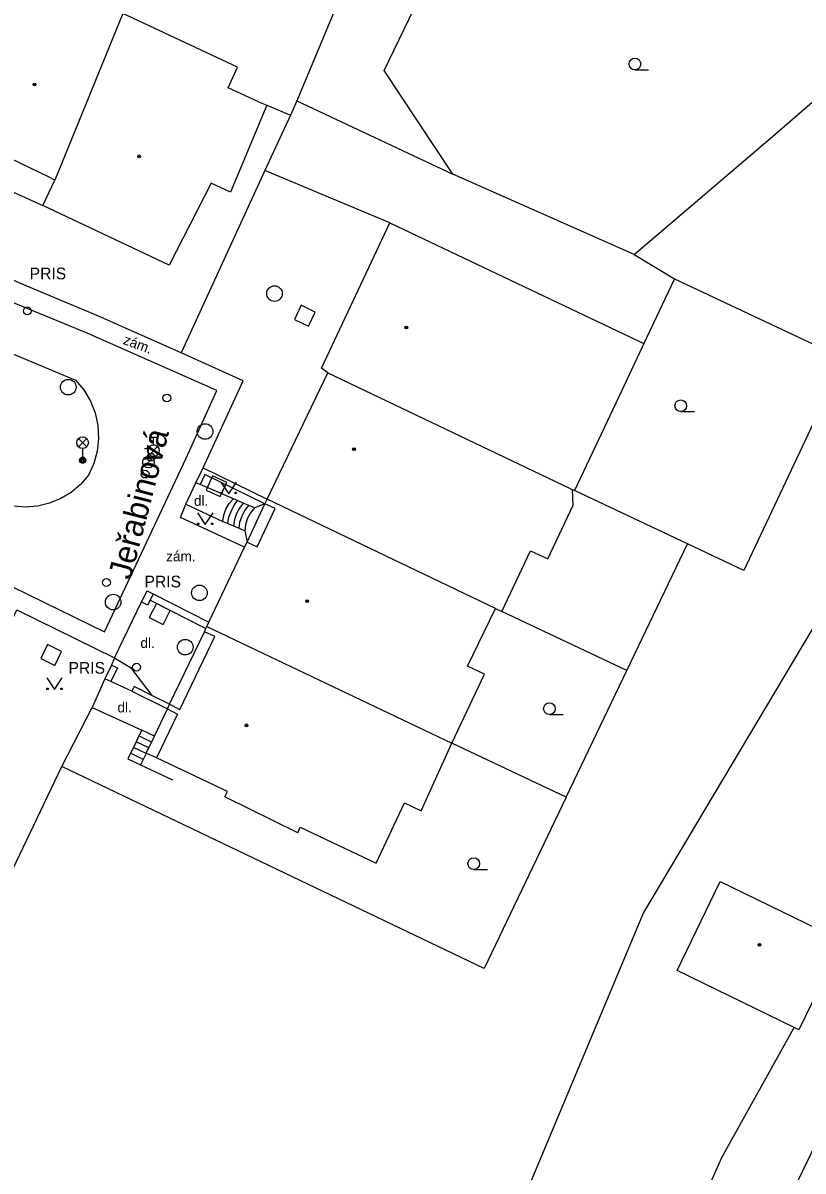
# Model space of a CAD drawing. Extents: x -600309 to -598967, y -1161267 to -1160292.
# Drawn here: x -599887.4 to -599837.4, y -1160784.7 to -1160711.1 of the extents above; entities that cross this region are included whole.
import ezdxf

# ---------------------------------------------------------------- set-up
doc = ezdxf.new("R2010")
doc.units = 0
for name, color, linetype in [('Level 10', 7, 'Continuous'), ('Level 11', 7, 'Continuous'), ('Level 24', 7, 'Continuous'), ('Level 26', 7, 'Continuous'), ('Level 27', 7, 'Continuous'), ('Level 28', 7, 'Continuous'), ('Level 33', 7, 'Continuous'), ('Level 36', 7, 'Continuous'), ('Level 39', 7, 'Continuous'), ('Level 40', 7, 'Continuous'), ('Level 42', 7, 'Continuous'), ('Level 5', 7, 'Continuous'), ('Level 50', 7, 'Continuous'), ('Level 51', 7, 'Continuous'), ('Level 52', 7, 'Continuous')]:
    doc.layers.add(name, color=color, linetype=linetype)

msp = doc.modelspace()

# ---------------------------------------------------------------- linework, layer by layer
at = {"layer": 'Level 10'}
for points in [[(-599941.84, -1160720.95), (-599921.83, -1160730.68), (-599912.84, -1160735.04), (-599897.82, -1160742.4699), (-599882.1599, -1160750.1), (-599876.92, -1160738.9699), (-599874.96, -1160734.65), (-599883.28, -1160730.96), (-599891.87, -1160727.45), (-599900.5, -1160724)], [(-599902.28, -1160726.6), (-599894.83, -1160729.46), (-599884.02, -1160733.98)], [(-599884.02, -1160733.98), (-599883.49, -1160734.61), (-599883.07, -1160735.32), (-599882.77, -1160736.08), (-599882.59, -1160736.89), (-599882.55, -1160737.71), (-599882.63, -1160738.53), (-599882.85, -1160739.32), (-599883.19, -1160740.07), (-599883.7, -1160740.6599), (-599884.3, -1160741.17), (-599884.9699, -1160741.57), (-599885.69, -1160741.87), (-599886.45, -1160742.05), (-599887.23, -1160742.11), (-599888.01, -1160742.05), (-599888.77, -1160741.87)]]:
    msp.add_lwpolyline(points, dxfattribs=at)
at = {"layer": 'Level 11'}
for points in [[(-599871.77, -1160716.37), (-599870.25, -1160717)], [(-599863.88, -1160723.9), (-599871.89, -1160720.55)], [(-599890.92, -1160726.29), (-599888.65, -1160721.63), (-599886.12, -1160722.79)], [(-599877.26, -1160732.23), (-599882.54, -1160729.87), (-599887.59, -1160727.77), (-599888.2199, -1160727.48)], [(-599875.85, -1160739.6), (-599873.27, -1160734.02), (-599877.26, -1160732.23)], [(-599876.32, -1160740.55), (-599875.85, -1160739.6)], [(-599871.88, -1160741.9), (-599875.73, -1160740.03), (-599876.04, -1160740.67)], [(-599875.85, -1160739.6), (-599871.74, -1160741.6)], [(-599876.95, -1160741.93), (-599876.32, -1160740.55)], [(-599876.04, -1160740.67), (-599876.32, -1160740.55)], [(-599873.9, -1160741.59), (-599876.04, -1160740.67)], [(-599874.57, -1160743.03), (-599874.52, -1160742.63), (-599874.38, -1160742.24), (-599874.17, -1160741.89), (-599873.9, -1160741.59)], [(-599874.27, -1160743.1599), (-599874.19, -1160742.77), (-599874.05, -1160742.39), (-599873.87, -1160742.03), (-599873.65, -1160741.7)], [(-599873.65, -1160741.7), (-599873.9, -1160741.59)], [(-599873.28, -1160741.86), (-599873.65, -1160741.7)], [(-599873.19, -1160744.69), (-599877.3, -1160742.79), (-599876.95, -1160741.93)], [(-599876.95, -1160741.93), (-599874.57, -1160743.03)], [(-599873.28, -1160741.86), (-599873.52, -1160742.18), (-599873.7, -1160742.53), (-599873.83, -1160742.9099), (-599873.9, -1160743.32)], [(-599873.54, -1160743.4699), (-599873.48, -1160743.07), (-599873.35, -1160742.68), (-599873.1599, -1160742.33), (-599872.9099, -1160742.01)], [(-599872.9099, -1160742.01), (-599873.28, -1160741.86)], [(-599872.54, -1160742.17), (-599872.81, -1160742.48), (-599873, -1160742.83), (-599873.12, -1160743.2199), (-599873.1599, -1160743.63)], [(-599872.54, -1160742.17), (-599872.9099, -1160742.01)], [(-599871.88, -1160741.9), (-599872.54, -1160742.17)], [(-599874.57, -1160743.03), (-599874.27, -1160743.1599)], [(-599874.27, -1160743.1599), (-599873.9, -1160743.32)], [(-599873.9, -1160743.32), (-599873.54, -1160743.4699)], [(-599873.54, -1160743.4699), (-599873.1599, -1160743.63)], [(-599873.1599, -1160743.63), (-599873.03, -1160744.36)], [(-599881.52, -1160751.78), (-599879.8, -1160748.19), (-599879.44, -1160747.4699), (-599879.04, -1160747.67), (-599875.4699, -1160749.49)], [(-599879.24, -1160748.08), (-599875.6599, -1160749.9)], [(-599890.39, -1160754.18), (-599887.79, -1160748.69), (-599881.52, -1160751.78)], [(-599881.52, -1160751.78), (-599881.7199, -1160752.25), (-599882.14, -1160753.11)], [(-599881.52, -1160751.78), (-599880.5, -1160752.4), (-599879.14, -1160754.18)], [(-599882.14, -1160753.11), (-599882.96, -1160754.95)], [(-599880.42, -1160753.9099), (-599881.76, -1160753.29), (-599882.14, -1160753.11)], [(-599879.14, -1160754.18), (-599880.27, -1160753.61), (-599880.42, -1160753.9099)], [(-599880.42, -1160753.9099), (-599878.13, -1160755.05)], [(-599877.99, -1160754.75), (-599879.14, -1160754.18)], [(-599882.96, -1160754.95), (-599879.78, -1160756.4099)], [(-599879.78, -1160756.4099), (-599879.96, -1160756.78)], [(-599878.9699, -1160756.8), (-599879.78, -1160756.4099)], [(-599880.13, -1160757.15), (-599880.31, -1160757.52)], [(-599879.96, -1160756.78), (-599880.13, -1160757.15)], [(-599879.33, -1160757.54), (-599880.13, -1160757.15)], [(-599879.15, -1160757.17), (-599879.96, -1160756.78)], [(-599880.49, -1160757.89), (-599880.6599, -1160758.25), (-599879.85, -1160758.63)], [(-599880.31, -1160757.52), (-599880.49, -1160757.89)], [(-599879.68, -1160758.28), (-599880.49, -1160757.89)], [(-599879.5, -1160757.9099), (-599880.31, -1160757.52)], [(-599879.5, -1160757.9099), (-599879.68, -1160758.28)], [(-599879.49, -1160757.88), (-599879.5, -1160757.9099)], [(-599879.68, -1160758.28), (-599879.85, -1160758.63)], [(-599879.85, -1160758.63), (-599877.8, -1160759.59)]]:
    msp.add_lwpolyline(points, dxfattribs=at)
at = {"layer": 'Level 24'}
for points in [[(-599879.4, -1160748.39), (-599879.8, -1160748.19)], [(-599879.04, -1160747.67), (-599879.24, -1160748.08), (-599879.4, -1160748.39)], [(-599881.34, -1160752.42), (-599881.76, -1160753.29)], [(-599881.7199, -1160752.25), (-599881.34, -1160752.42)]]:
    msp.add_lwpolyline(points, dxfattribs=at)
at = {"layer": 'Level 26'}
for points in [[(-599869.0934, -1160730.5163), (-599868.6637, -1160729.6134), (-599869.5666, -1160729.1837), (-599869.9963, -1160730.0866)], [(-599874.3263, -1160740.536), (-599875.234, -1160740.1163), (-599875.6537, -1160741.024), (-599874.746, -1160741.4437)], [(-599877.9477, -1160748.7409), (-599878.8391, -1160748.2877), (-599879.2923, -1160749.1791), (-599878.4009, -1160749.6323)], [(-599886.2495, -1160751.8174), (-599885.3526, -1160752.2595), (-599884.9105, -1160751.3626), (-599885.8074, -1160750.9205)]]:
    msp.add_lwpolyline(points, close=True, dxfattribs=at)
at = {"layer": 'Level 27'}
for centre in [(-599871.27, -1160728.43), (-599884.49, -1160734.43), (-599875.7199, -1160737.27), (-599876.08, -1160747.61), (-599881.61, -1160748.2), (-599876.99, -1160751.09)]:
    msp.add_circle(centre, 0.5, dxfattribs=at)
at = {"layer": 'Level 28'}
for p, q in [((-599879.28, -1160737.625), (-599878.78, -1160737.625)), ((-599879.03, -1160738.125), (-599879.03, -1160737.625)), ((-599879.6, -1160738.355), (-599879.1, -1160738.355)), ((-599879.35, -1160738.855), (-599879.35, -1160738.355)), ((-599879.288, -1160738.772), (-599878.758, -1160738.242)), ((-599879.608, -1160739.502), (-599879.078, -1160738.972))]:
    msp.add_line(p, q, dxfattribs=at)
for centre, radius in [((-599887.11, -1160729.54), 0.25), ((-599878.17, -1160735.12), 0.25), ((-599879.18, -1160738.92), 0.25), ((-599879.03, -1160738.5), 0.375), ((-599879.35, -1160739.23), 0.375), ((-599879.56, -1160740), 0.25), ((-599882.04, -1160746.95), 0.25), ((-599880.11, -1160752.37), 0.25)]:
    msp.add_circle(centre, radius, dxfattribs=at)
at = {"layer": 'Level 33'}
for p, q in [((-599883.835, -1160738.25), (-599883.305, -1160737.72)), ((-599883.835, -1160737.72), (-599883.305, -1160738.25)), ((-599883.57, -1160738.36), (-599883.57, -1160739.11))]:
    msp.add_line(p, q, dxfattribs=at)
for centre, radius in [((-599883.57, -1160737.985), 0.375), ((-599883.57, -1160739.11), 0.2), ((-599883.57, -1160739.11), 0.1445), ((-599883.57, -1160739.11), 0.0876)]:
    msp.add_circle(centre, radius, dxfattribs=at)
at = {"layer": 'Level 36'}
for p, q in [((-599848.17, -1160714.0949), (-599847.295, -1160714.0949)), ((-599845.23, -1160735.995), (-599844.355, -1160735.995)), ((-599853.65, -1160755.405), (-599852.775, -1160755.405)), ((-599858.5, -1160765.335), (-599857.625, -1160765.335))]:
    msp.add_line(p, q, dxfattribs=at)
for points in [[(-599874.7, -1160740.51), (-599874.2, -1160741.26), (-599873.7, -1160740.51)], [(-599876.21, -1160742.49), (-599875.71, -1160743.24), (-599875.21, -1160742.49)], [(-599885.87, -1160753.06), (-599885.37, -1160753.81), (-599884.87, -1160753.06)]]:
    msp.add_lwpolyline(points, dxfattribs=at)
for centre, radius in [((-599848.1701, -1160713.7198), 0.375), ((-599845.2301, -1160735.6199), 0.375), ((-599874.6502, -1160741.2098), 0.05), ((-599873.7508, -1160741.2098), 0.05), ((-599876.1602, -1160743.1898), 0.05), ((-599875.2608, -1160743.1898), 0.05), ((-599885.8202, -1160753.7598), 0.05), ((-599884.9208, -1160753.7598), 0.05), ((-599853.6501, -1160755.0299), 0.375), ((-599858.5001, -1160764.9599), 0.375)]:
    msp.add_circle(centre, radius, dxfattribs=at)
at = {"layer": 'Level 39'}
for centre, radius in [((-599886.65, -1160715.04), 0.09), ((-599886.65, -1160715.04), 0.0398), ((-599879.94, -1160719.64), 0.09), ((-599879.94, -1160719.64), 0.0398), ((-599862.82, -1160730.61), 0.09), ((-599862.82, -1160730.61), 0.0398), ((-599866.17, -1160738.4), 0.09), ((-599866.17, -1160738.4), 0.0398), ((-599869.17, -1160748.14), 0.09), ((-599869.17, -1160748.14), 0.0398), ((-599873.06, -1160756.1), 0.09), ((-599873.06, -1160756.1), 0.0398), ((-599840.18, -1160770.1599), 0.09), ((-599840.18, -1160770.1599), 0.0398)]:
    msp.add_circle(centre, radius, dxfattribs=at)
at = {"layer": 'Level 5'}
for points in [[(-599880.98, -1160710.48), (-599885.35, -1160721.1599)], [(-599873.63, -1160713.93), (-599880.98, -1160710.48)], [(-599874.24, -1160715.24), (-599873.63, -1160713.93)], [(-599872.3, -1160716.15), (-599874.24, -1160715.24)], [(-599871.77, -1160716.37), (-599874.09, -1160721.93)], [(-599872.3, -1160716.15), (-599871.77, -1160716.37)], [(-599885.76, -1160720.96), (-599888.73, -1160719.53)], [(-599886.12, -1160722.79), (-599885.35, -1160721.1599)], [(-599885.35, -1160721.1599), (-599885.76, -1160720.96)], [(-599875.32, -1160721.36), (-599878.01, -1160726.61)], [(-599874.09, -1160721.93), (-599875.32, -1160721.36)], [(-599878.01, -1160726.61), (-599886.12, -1160722.79)], [(-599868.26, -1160733.2199), (-599863.88, -1160723.9)], [(-599863.88, -1160723.9), (-599847.6, -1160731.63)], [(-599847.73, -1160731.9), (-599849.21, -1160735.05)], [(-599847.6, -1160731.63), (-599847.73, -1160731.9)], [(-599871.74, -1160741.6), (-599867.85, -1160733.51)], [(-599867.85, -1160733.51), (-599868.26, -1160733.2199)], [(-599867.85, -1160733.51), (-599852.33, -1160740.92)], [(-599849.21, -1160735.05), (-599852.04, -1160741.05)], [(-599852.33, -1160740.92), (-599852.1599, -1160741)], [(-599852.04, -1160741.05), (-599852.1599, -1160741)], [(-599852.13, -1160742), (-599852.1599, -1160741)], [(-599871.88, -1160741.9), (-599871.74, -1160741.6)], [(-599857.11, -1160748.61), (-599871.74, -1160741.6)], [(-599873.03, -1160744.36), (-599871.88, -1160741.9)], [(-599872.37, -1160744.67), (-599871.2199, -1160742.21)], [(-599871.2199, -1160742.21), (-599871.88, -1160741.9)], [(-599853.75, -1160745.44), (-599852.13, -1160742)], [(-599875.4699, -1160749.49), (-599873.19, -1160744.69)], [(-599873.19, -1160744.69), (-599873.03, -1160744.36)], [(-599873.03, -1160744.36), (-599872.37, -1160744.67)], [(-599856.69, -1160748.81), (-599854.86, -1160744.92)], [(-599854.86, -1160744.92), (-599853.75, -1160745.44)], [(-599858.9, -1160752.3), (-599857.11, -1160748.61)], [(-599857.11, -1160748.61), (-599856.69, -1160748.81)], [(-599875.6599, -1160749.9), (-599875.6, -1160749.77)], [(-599875.6, -1160749.77), (-599875.4699, -1160749.49)], [(-599875.6, -1160749.77), (-599859.9, -1160757.25)], [(-599877.99, -1160754.75), (-599875.76, -1160750.1)], [(-599877.34, -1160755.08), (-599875.1, -1160750.4099)], [(-599875.76, -1160750.1), (-599875.6599, -1160749.9)], [(-599875.1, -1160750.4099), (-599875.76, -1160750.1)], [(-599857.81, -1160752.82), (-599858.9, -1160752.3)], [(-599859.9, -1160757.25), (-599857.81, -1160752.82)], [(-599878.13, -1160755.05), (-599877.99, -1160754.75)], [(-599877.99, -1160754.75), (-599877.34, -1160755.08)], [(-599878.9699, -1160756.8), (-599878.13, -1160755.05)], [(-599877.48, -1160755.38), (-599878.83, -1160758.19)], [(-599878.13, -1160755.05), (-599877.48, -1160755.38)], [(-599879.49, -1160757.88), (-599878.9699, -1160756.8)], [(-599878.83, -1160758.19), (-599879.49, -1160757.88)], [(-599861.87, -1160761.57), (-599859.9, -1160757.25)], [(-599874.28, -1160760.33), (-599878.83, -1160758.19)], [(-599874.46, -1160760.69), (-599874.28, -1160760.33)], [(-599869.78, -1160762.98), (-599874.46, -1160760.69)], [(-599864.75, -1160764.92), (-599862.94, -1160761.07)], [(-599862.94, -1160761.07), (-599861.87, -1160761.57)], [(-599869.78, -1160762.98), (-599869.62, -1160762.62)], [(-599869.62, -1160762.62), (-599864.75, -1160764.92)]]:
    msp.add_lwpolyline(points, dxfattribs=at)
at = {"layer": 'Level 51'}
for points in [[(-599864.24, -1160714.13), (-599859.1599, -1160703.6)], [(-599867.1599, -1160709.69), (-599869.83, -1160716.08)], [(-599839.2, -1160718.23), (-599832.19, -1160712.17)], [(-599859.84, -1160720.79), (-599864.24, -1160714.13)], [(-599869.83, -1160716.08), (-599870.25, -1160717), (-599871.89, -1160720.55), (-599877.26, -1160732.23)], [(-599869.83, -1160716.08), (-599859.84, -1160720.79)], [(-599848.21, -1160725.92), (-599839.2, -1160718.23)], [(-599848.21, -1160725.92), (-599859.84, -1160720.79)], [(-599848.21, -1160725.92), (-599845.64, -1160727.48)], [(-599845.64, -1160727.48), (-599847.6, -1160731.63)], [(-599845.64, -1160727.48), (-599834.79, -1160732.6), (-599841.18, -1160746.17), (-599844.8, -1160744.46)], [(-599844.8, -1160744.46), (-599852.04, -1160741.05)], [(-599848.69, -1160752.58), (-599844.8, -1160744.46)], [(-599848.69, -1160752.58), (-599856.69, -1160748.81)], [(-599836.29, -1160749.09), (-599847.63, -1160768.09)], [(-599852.58, -1160760.7), (-599848.69, -1160752.58)], [(-599822.68, -1160754.06), (-599841.34, -1160792.79)], [(-599884.9, -1160758.73), (-599882.96, -1160754.95)], [(-599852.58, -1160760.7), (-599859.9, -1160757.25)], [(-599895.27, -1160780.39), (-599884.9, -1160758.73)], [(-599857.84, -1160771.68), (-599884.9, -1160758.73)], [(-599852.58, -1160760.7), (-599857.84, -1160771.68)], [(-599847.63, -1160768.09), (-599866.24, -1160812.57)], [(-599842.61, -1160783.8), (-599837.9699, -1160775.45)], [(-599855.88, -1160813.7199), (-599842.61, -1160783.8)]]:
    msp.add_lwpolyline(points, dxfattribs=at)
at = {"layer": 'Level 52'}
for points in [[(-599845.4699, -1160771.81), (-599842.7, -1160766.11)], [(-599842.7, -1160766.11), (-599834.89, -1160769.9099)], [(-599834.89, -1160769.9099), (-599837.6599, -1160775.6)], [(-599837.9699, -1160775.45), (-599845.4699, -1160771.81)], [(-599837.6599, -1160775.6), (-599837.9699, -1160775.45)]]:
    msp.add_lwpolyline(points, dxfattribs=at)

# ---------------------------------------------------------------- texts
at = {"layer": 'Level 40'}
msp.add_text('zám.', height=0.65, rotation=339.76, dxfattribs=at).set_placement((-599881.02, -1160731.65))
for s, p in [('dl.', (-599876.43, -1160742.03)), ('zám.', (-599878.21, -1160745.59)), ('dl.', (-599879.86, -1160751.14)), ('dl.', (-599881.33, -1160755.27))]:
    msp.add_text(s, height=0.65, dxfattribs=at).set_placement(p)
at = {"layer": 'Level 42'}
for p in [(-599886.96, -1160727.52), (-599879.6, -1160747.26), (-599884.4699, -1160752.79)]:
    msp.add_text('PRIS', height=0.75, dxfattribs=at).set_placement(p)
at = {"layer": 'Level 50'}
msp.add_text('Jeřabinová', height=1.5, rotation=75.441416, dxfattribs=at).set_placement((-599880.4888, -1160746.8219))

doc.saveas('drawing.dxf')
